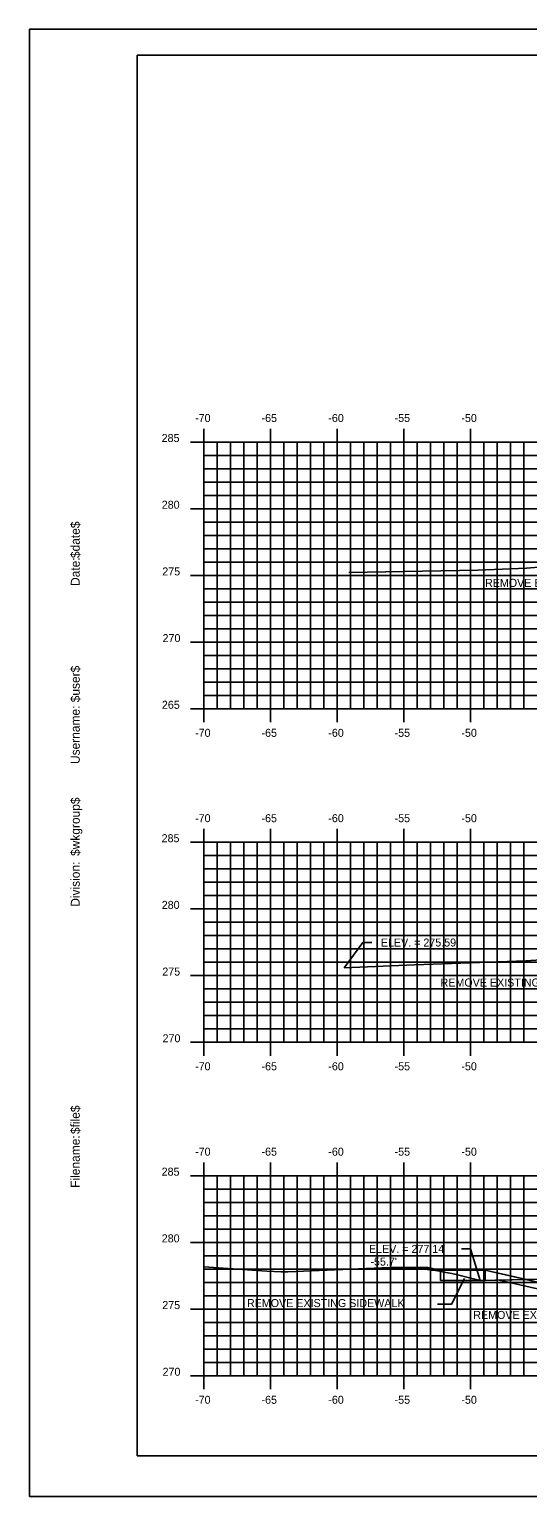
# Model space of a CAD drawing. Extents: x 854008 to 854178, y 366268 to 366378.
# Drawn here: x 854008 to 854045.4, y 366268.2 to 366378.2 of the extents above; entities that cross this region are included whole.
import ezdxf

# ---------------------------------------------------------------- set-up
doc = ezdxf.new("R2010")
doc.units = 0
for name, color, linetype in [('ANNOTATION', 7, 'Continuous'), ('BORDER', 7, 'Continuous'), ('D_Roadway_FinishedGrade', 7, 'Continuous'), ('D_Roadway_SubGrade', 7, 'Continuous'), ('D_Text_Standard', 7, 'Continuous'), ('H_V ANNOTATION', 7, 'Continuous'), ('JUNK COM EXC', 7, 'Continuous'), ('JUNK FILL', 7, 'Continuous'), ('MAJOR', 7, 'Continuous'), ('MINOR', 7, 'Continuous'), ('PLOT BOUNDARY', 7, 'Continuous'), ('S_Roadway_Centerline', 7, 'Continuous')]:
    doc.layers.add(name, color=color, linetype=linetype)

msp = doc.modelspace()

# ---------------------------------------------------------------- linework, layer by layer
at = {"layer": 'ANNOTATION'}
msp.add_lwpolyline([(854038.61, 366282.62), (854039.67, 366282.62), (854040.64, 366284.53)], dxfattribs=at)
at = {"layer": 'BORDER'}
for p, q in [((854176.1, 366376.24), (854016.1, 366376.24)), ((854016.1, 366376.24), (854016.1, 366271.24)), ((854016.1, 366271.24), (854176.1, 366271.24))]:
    msp.add_line(p, q, dxfattribs=at)
at = {"layer": 'D_Roadway_FinishedGrade'}
for p in [(854040.31, 366284.75), (854067.1, 366284.88)]:
    msp.add_line(p, (854041.81, 366284.38), dxfattribs=at)
msp.add_arc((854035.46, 366265.35), 20, 75.9638, 90.3035, dxfattribs=at)
at = {"layer": 'D_Roadway_SubGrade'}
msp.add_lwpolyline([(854043.23, 366284.41), (854046.34, 366283.7), (854046.88, 366283.57), (854050.76, 366283.59), (854057.27, 366283.69), (854058.44, 366283.75), (854067.1, 366283.91)], dxfattribs=at)
at = {"layer": 'D_Text_Standard'}
for points in [[(854031.62, 366307.83), (854033.01, 366309.72), (854033.69, 366309.72)], [(854041.81, 366284.38), (854041.1, 366286.75), (854040.42, 366286.75)]]:
    msp.add_lwpolyline(points, dxfattribs=at)
at = {"layer": 'JUNK COM EXC'}
for points in [[(854045.3, 366284.45), (854042.19, 366285.16), (854041.61, 366285.15), (854038.85, 366285.16), (854037.87, 366285.36), (854035.36, 366285.35)], [(854040.31, 366284.75), (854041.81, 366284.38), (854045.3, 366284.45)]]:
    msp.add_lwpolyline(points, dxfattribs=at)
msp.add_arc((854035.46, 366265.35), 20, 75.9638, 90.3035, dxfattribs=at)
at = {"layer": 'JUNK FILL'}
msp.add_lwpolyline([(854067.1, 366284.41), (854067.1, 366284.88), (854067.1, 366284.88), (854045.3, 366284.45), (854046.45, 366284.19), (854046.94, 366284.07), (854050.76, 366284.09), (854057.25, 366284.19), (854058.42, 366284.25), (854067.1, 366284.41)], dxfattribs=at)
at = {"layer": 'MAJOR'}
for p, q in [((854021.1, 366348.24), (854021.1, 366347.24)), ((854026.1, 366348.24), (854026.1, 366347.24)), ((854031.1, 366348.24), (854031.1, 366347.24)), ((854036.1, 366348.24), (854036.1, 366347.24)), ((854041.1, 366348.24), (854041.1, 366347.24)), ((854020.1, 366347.24), (854021.1, 366347.24)), ((854021.1, 366347.24), (854161.1, 366347.24)), ((854021.1, 366327.24), (854021.1, 366347.24)), ((854021.1, 366327.24), (854021.1, 366347.24)), ((854021.1, 366347.24), (854161.1, 366347.24)), ((854026.1, 366327.24), (854026.1, 366347.24)), ((854031.1, 366327.24), (854031.1, 366347.24)), ((854036.1, 366327.24), (854036.1, 366347.24)), ((854041.1, 366327.24), (854041.1, 366347.24)), ((854020.1, 366342.24), (854021.1, 366342.24)), ((854021.1, 366342.24), (854161.1, 366342.24)), ((854020.1, 366337.24), (854021.1, 366337.24)), ((854021.1, 366337.24), (854161.1, 366337.24)), ((854020.1, 366332.24), (854021.1, 366332.24)), ((854021.1, 366332.24), (854161.1, 366332.24)), ((854020.1, 366327.24), (854021.1, 366327.24)), ((854021.1, 366327.24), (854161.1, 366327.24)), ((854021.1, 366327.24), (854161.1, 366327.24)), ((854021.1, 366326.23), (854021.1, 366327.24)), ((854026.1, 366326.23), (854026.1, 366327.24)), ((854031.1, 366326.23), (854031.1, 366327.24)), ((854036.1, 366326.23), (854036.1, 366327.24)), ((854041.1, 366326.23), (854041.1, 366327.24)), ((854021.1, 366318.24), (854021.1, 366317.24)), ((854026.1, 366318.24), (854026.1, 366317.24)), ((854031.1, 366318.24), (854031.1, 366317.24)), ((854036.1, 366318.24), (854036.1, 366317.24)), ((854041.1, 366318.24), (854041.1, 366317.24)), ((854020.1, 366317.24), (854021.1, 366317.24)), ((854021.1, 366317.24), (854161.1, 366317.24)), ((854021.1, 366302.24), (854021.1, 366317.24)), ((854021.1, 366302.24), (854021.1, 366317.24)), ((854021.1, 366317.24), (854161.1, 366317.24)), ((854026.1, 366302.24), (854026.1, 366317.24)), ((854031.1, 366302.24), (854031.1, 366317.24)), ((854036.1, 366302.24), (854036.1, 366317.24)), ((854041.1, 366302.24), (854041.1, 366317.24)), ((854020.1, 366312.24), (854021.1, 366312.24)), ((854021.1, 366312.24), (854161.1, 366312.24)), ((854020.1, 366307.24), (854021.1, 366307.24)), ((854021.1, 366307.24), (854161.1, 366307.24)), ((854020.1, 366302.24), (854021.1, 366302.24)), ((854021.1, 366302.24), (854161.1, 366302.24)), ((854021.1, 366302.24), (854161.1, 366302.24)), ((854021.1, 366301.23), (854021.1, 366302.24)), ((854026.1, 366301.23), (854026.1, 366302.24)), ((854031.1, 366301.23), (854031.1, 366302.24)), ((854036.1, 366301.23), (854036.1, 366302.24)), ((854041.1, 366301.23), (854041.1, 366302.24)), ((854021.1, 366293.24), (854021.1, 366292.24)), ((854026.1, 366293.24), (854026.1, 366292.24)), ((854031.1, 366293.24), (854031.1, 366292.24)), ((854036.1, 366293.24), (854036.1, 366292.24)), ((854041.1, 366293.24), (854041.1, 366292.24)), ((854020.1, 366292.24), (854021.1, 366292.24)), ((854021.1, 366292.24), (854161.1, 366292.24)), ((854021.1, 366277.24), (854021.1, 366292.24)), ((854021.1, 366277.24), (854021.1, 366292.24)), ((854021.1, 366292.24), (854161.1, 366292.24)), ((854026.1, 366277.24), (854026.1, 366292.24)), ((854031.1, 366277.24), (854031.1, 366292.24)), ((854036.1, 366277.24), (854036.1, 366292.24)), ((854041.1, 366277.24), (854041.1, 366292.24)), ((854020.1, 366287.24), (854021.1, 366287.24)), ((854021.1, 366287.24), (854161.1, 366287.24)), ((854020.1, 366282.24), (854021.1, 366282.24)), ((854021.1, 366282.24), (854161.1, 366282.24)), ((854020.1, 366277.24), (854021.1, 366277.24)), ((854021.1, 366277.24), (854161.1, 366277.24)), ((854021.1, 366277.24), (854161.1, 366277.24)), ((854021.1, 366276.23), (854021.1, 366277.24)), ((854026.1, 366276.23), (854026.1, 366277.24)), ((854031.1, 366276.23), (854031.1, 366277.24)), ((854036.1, 366276.23), (854036.1, 366277.24)), ((854041.1, 366276.23), (854041.1, 366277.24))]:
    msp.add_line(p, q, dxfattribs=at)
at = {"layer": 'MINOR'}
for p, q in [((854021.1, 366327.24), (854021.1, 366347.24)), ((854021.1, 366346.24), (854161.1, 366346.24)), ((854021.1, 366346.24), (854022.11, 366346.24)), ((854022.1, 366327.24), (854022.1, 366347.24)), ((854023.1, 366327.24), (854023.1, 366347.24)), ((854024.1, 366327.24), (854024.1, 366347.24)), ((854025.1, 366327.24), (854025.1, 366347.24)), ((854027.1, 366327.24), (854027.1, 366347.24)), ((854028.1, 366327.24), (854028.1, 366347.24)), ((854029.1, 366327.24), (854029.1, 366347.24)), ((854030.1, 366327.24), (854030.1, 366347.24)), ((854032.1, 366327.24), (854032.1, 366347.24)), ((854033.1, 366327.24), (854033.1, 366347.24)), ((854034.1, 366327.24), (854034.1, 366347.24)), ((854035.1, 366327.24), (854035.1, 366347.24)), ((854037.1, 366327.24), (854037.1, 366347.24)), ((854038.1, 366327.24), (854038.1, 366347.24)), ((854039.1, 366327.24), (854039.1, 366347.24)), ((854040.1, 366327.24), (854040.1, 366347.24)), ((854042.1, 366327.24), (854042.1, 366347.24)), ((854043.1, 366327.24), (854043.1, 366347.24)), ((854044.1, 366327.24), (854044.1, 366347.24)), ((854045.1, 366327.24), (854045.1, 366347.24)), ((854021.1, 366345.24), (854161.1, 366345.24)), ((854021.1, 366345.24), (854022.11, 366345.24)), ((854021.1, 366344.24), (854161.1, 366344.24)), ((854021.1, 366344.24), (854022.11, 366344.24)), ((854021.1, 366343.24), (854161.1, 366343.24)), ((854021.1, 366343.24), (854022.11, 366343.24)), ((854021.1, 366341.24), (854161.1, 366341.24)), ((854021.1, 366341.24), (854022.11, 366341.24)), ((854021.1, 366340.24), (854161.1, 366340.24)), ((854021.1, 366340.24), (854022.11, 366340.24)), ((854021.1, 366339.24), (854161.1, 366339.24)), ((854021.1, 366339.24), (854022.11, 366339.24)), ((854021.1, 366338.24), (854161.1, 366338.24)), ((854021.1, 366338.24), (854022.11, 366338.24)), ((854021.1, 366336.24), (854161.1, 366336.24)), ((854021.1, 366336.24), (854022.11, 366336.24)), ((854021.1, 366335.24), (854161.1, 366335.24)), ((854021.1, 366335.24), (854022.11, 366335.24)), ((854021.1, 366334.24), (854161.1, 366334.24)), ((854021.1, 366334.24), (854022.11, 366334.24)), ((854021.1, 366333.24), (854161.1, 366333.24)), ((854021.1, 366333.24), (854022.11, 366333.24)), ((854021.1, 366331.24), (854161.1, 366331.24)), ((854021.1, 366331.24), (854022.11, 366331.24)), ((854021.1, 366330.24), (854161.1, 366330.24)), ((854021.1, 366330.24), (854022.11, 366330.24)), ((854021.1, 366329.24), (854161.1, 366329.24)), ((854021.1, 366329.24), (854022.11, 366329.24)), ((854021.1, 366328.24), (854161.1, 366328.24)), ((854021.1, 366328.24), (854022.11, 366328.24)), ((854022.1, 366302.24), (854022.1, 366317.24)), ((854023.1, 366302.24), (854023.1, 366317.24)), ((854024.1, 366302.24), (854024.1, 366317.24)), ((854025.1, 366302.24), (854025.1, 366317.24)), ((854027.1, 366302.24), (854027.1, 366317.24)), ((854028.1, 366302.24), (854028.1, 366317.24)), ((854029.1, 366302.24), (854029.1, 366317.24)), ((854030.1, 366302.24), (854030.1, 366317.24)), ((854032.1, 366302.24), (854032.1, 366317.24)), ((854033.1, 366302.24), (854033.1, 366317.24)), ((854034.1, 366302.24), (854034.1, 366317.24)), ((854035.1, 366302.24), (854035.1, 366317.24)), ((854037.1, 366302.24), (854037.1, 366317.24)), ((854038.1, 366302.24), (854038.1, 366317.24)), ((854039.1, 366302.24), (854039.1, 366317.24)), ((854040.1, 366302.24), (854040.1, 366317.24)), ((854042.1, 366302.24), (854042.1, 366317.24)), ((854043.1, 366302.24), (854043.1, 366317.24)), ((854044.1, 366302.24), (854044.1, 366317.24)), ((854045.1, 366302.24), (854045.1, 366317.24)), ((854021.1, 366316.24), (854161.1, 366316.24)), ((854021.1, 366316.24), (854022.11, 366316.24)), ((854021.1, 366315.24), (854161.1, 366315.24)), ((854021.1, 366315.24), (854022.11, 366315.24)), ((854021.1, 366314.24), (854161.1, 366314.24)), ((854021.1, 366314.24), (854022.11, 366314.24)), ((854021.1, 366313.24), (854161.1, 366313.24)), ((854021.1, 366313.24), (854022.11, 366313.24)), ((854021.1, 366311.24), (854161.1, 366311.24)), ((854021.1, 366311.24), (854022.11, 366311.24)), ((854021.1, 366310.24), (854161.1, 366310.24)), ((854021.1, 366310.24), (854022.11, 366310.24)), ((854021.1, 366309.24), (854161.1, 366309.24)), ((854021.1, 366309.24), (854022.11, 366309.24)), ((854021.1, 366308.24), (854161.1, 366308.24)), ((854021.1, 366308.24), (854022.11, 366308.24)), ((854021.1, 366306.24), (854161.1, 366306.24)), ((854021.1, 366306.24), (854022.11, 366306.24)), ((854021.1, 366305.24), (854161.1, 366305.24)), ((854021.1, 366305.24), (854022.11, 366305.24)), ((854021.1, 366304.24), (854161.1, 366304.24)), ((854021.1, 366304.24), (854022.11, 366304.24)), ((854021.1, 366303.24), (854161.1, 366303.24)), ((854021.1, 366303.24), (854022.11, 366303.24)), ((854021.1, 366291.24), (854161.1, 366291.24)), ((854021.1, 366291.24), (854022.11, 366291.24)), ((854022.1, 366277.24), (854022.1, 366292.24)), ((854023.1, 366277.24), (854023.1, 366292.24)), ((854024.1, 366277.24), (854024.1, 366292.24)), ((854025.1, 366277.24), (854025.1, 366292.24)), ((854027.1, 366277.24), (854027.1, 366292.24)), ((854028.1, 366277.24), (854028.1, 366292.24)), ((854029.1, 366277.24), (854029.1, 366292.24)), ((854030.1, 366277.24), (854030.1, 366292.24)), ((854032.1, 366277.24), (854032.1, 366292.24)), ((854033.1, 366277.24), (854033.1, 366292.24)), ((854034.1, 366277.24), (854034.1, 366292.24)), ((854035.1, 366277.24), (854035.1, 366292.24)), ((854037.1, 366277.24), (854037.1, 366292.24)), ((854038.1, 366277.24), (854038.1, 366292.24)), ((854039.1, 366277.24), (854039.1, 366292.24)), ((854040.1, 366277.24), (854040.1, 366292.24)), ((854042.1, 366277.24), (854042.1, 366292.24)), ((854043.1, 366277.24), (854043.1, 366292.24)), ((854044.1, 366277.24), (854044.1, 366292.24)), ((854045.1, 366277.24), (854045.1, 366292.24)), ((854021.1, 366290.24), (854161.1, 366290.24)), ((854021.1, 366290.24), (854022.11, 366290.24)), ((854021.1, 366289.24), (854161.1, 366289.24)), ((854021.1, 366289.24), (854022.11, 366289.24)), ((854021.1, 366288.24), (854161.1, 366288.24)), ((854021.1, 366288.24), (854022.11, 366288.24)), ((854021.1, 366286.24), (854161.1, 366286.24)), ((854021.1, 366286.24), (854022.11, 366286.24)), ((854021.1, 366285.24), (854161.1, 366285.24)), ((854021.1, 366285.24), (854022.11, 366285.24)), ((854021.1, 366284.24), (854161.1, 366284.24)), ((854021.1, 366284.24), (854022.11, 366284.24)), ((854021.1, 366283.24), (854161.1, 366283.24)), ((854021.1, 366283.24), (854022.11, 366283.24)), ((854021.1, 366281.24), (854161.1, 366281.24)), ((854021.1, 366281.24), (854022.11, 366281.24)), ((854021.1, 366280.24), (854161.1, 366280.24)), ((854021.1, 366280.24), (854022.11, 366280.24)), ((854021.1, 366279.24), (854161.1, 366279.24)), ((854021.1, 366279.24), (854022.11, 366279.24)), ((854021.1, 366278.24), (854161.1, 366278.24)), ((854021.1, 366278.24), (854022.11, 366278.24))]:
    msp.add_line(p, q, dxfattribs=at)
at = {"layer": 'PLOT BOUNDARY'}
msp.add_lwpolyline([(854008.01, 366268.18), (854178.01, 366268.18), (854178.01, 366378.18), (854008.01, 366378.18)], close=True, dxfattribs=at)
at = {"layer": 'S_Roadway_Centerline'}
for p, q in [((854038.85, 366284.39), (854038.85, 366285.16)), ((854042.19, 366284.39), (854042.19, 366285.16))]:
    msp.add_line(p, q, dxfattribs=at)
for points in [[(854031.97, 366337.45), (854041.64, 366337.63), (854045.29, 366337.78), (854051.42, 366338.29)], [(854031.62, 366307.83), (854036.89, 366308.04), (854045.23, 366308.34), (854048.3, 366308.55)], [(854021.1, 366285.4), (854025.83, 366285.09), (854026.89, 366285.04), (854027.4, 366285.03), (854035.05, 366285.35), (854037.87, 366285.36), (854038.85, 366285.16), (854041.61, 366285.15), (854042.19, 366285.16), (854046.45, 366284.19)], [(854038.85, 366284.39), (854041.61, 366284.38), (854042.19, 366284.39)]]:
    msp.add_lwpolyline(points, dxfattribs=at)

# ---------------------------------------------------------------- texts
at = {"layer": 'ANNOTATION'}
for s, p in [('REMOVE EXISTING SIDEWALK', (854042.18, 366336.38)), ('REMOVE EXISTING SIDEWALK', (854038.85, 366306.42)), ('REMOVE EXISTING SIDEWALK', (854024.33, 366282.39)), ('REMOVE EXISTING PAVEMENT', (854041.3, 366281.5))]:
    msp.add_text(s, height=0.6, dxfattribs=at).set_placement(p)
at = {"layer": 'BORDER'}
for s, p in [('$date$', (854011.79, 366338.54)), ('Date:', (854011.79, 366336.45)), ('$user$', (854011.79, 366327.73)), ('Username:', (854011.79, 366323.1)), ('$wkgroup$', (854011.79, 366316.21)), ('Division:', (854011.79, 366312.4)), ('$file$', (854011.79, 366295.36)), ('Filename:', (854011.79, 366291.33))]:
    msp.add_text(s, height=0.67, rotation=90, dxfattribs=at).set_placement(p)
at = {"layer": 'D_Text_Standard'}
for s, p in [('ELEV. = 275.59', (854034.37, 366309.42)), ('ELEV. = 277.14', (854033.48, 366286.45)), ("-55.7'", (854033.59, 366285.5))]:
    msp.add_text(s, height=0.6, dxfattribs=at).set_placement(p)
at = {"layer": 'H_V ANNOTATION'}
for s, p in [('-70', (854020.44, 366348.74)), ('-65', (854025.42, 366348.74)), ('-60', (854030.43, 366348.74)), ('-55', (854035.4, 366348.74)), ('-50', (854040.41, 366348.74)), ('285', (854017.93, 366347.24)), ('280', (854017.94, 366342.24)), ('275', (854017.98, 366337.24)), ('270', (854018, 366332.24)), ('265', (854017.95, 366327.24)), ('-70', (854020.44, 366325.14)), ('-65', (854025.42, 366325.14)), ('-60', (854030.43, 366325.14)), ('-55', (854035.4, 366325.14)), ('-50', (854040.41, 366325.14)), ('-70', (854020.44, 366318.74)), ('-65', (854025.42, 366318.74)), ('-60', (854030.43, 366318.74)), ('-55', (854035.4, 366318.74)), ('-50', (854040.41, 366318.74)), ('285', (854017.93, 366317.24)), ('280', (854017.94, 366312.24)), ('275', (854017.98, 366307.24)), ('270', (854018, 366302.24)), ('-70', (854020.44, 366300.14)), ('-65', (854025.42, 366300.14)), ('-60', (854030.43, 366300.14)), ('-55', (854035.4, 366300.14)), ('-50', (854040.41, 366300.14)), ('-70', (854020.44, 366293.74)), ('-65', (854025.42, 366293.74)), ('-60', (854030.43, 366293.74)), ('-55', (854035.4, 366293.74)), ('-50', (854040.41, 366293.74)), ('285', (854017.93, 366292.24)), ('280', (854017.94, 366287.24)), ('275', (854017.98, 366282.24)), ('270', (854018, 366277.24)), ('-70', (854020.44, 366275.14)), ('-65', (854025.42, 366275.14)), ('-60', (854030.43, 366275.14)), ('-55', (854035.4, 366275.14)), ('-50', (854040.41, 366275.14))]:
    msp.add_text(s, height=0.6, dxfattribs=at).set_placement(p)
at = {"layer": 'MAJOR'}
for p in [(854021.1, 366327.24), (854021.1, 366302.24), (854021.1, 366277.24)]:
    msp.add_text('-', height=0.00000006, rotation=53.1301, dxfattribs=at).set_placement(p)

doc.saveas('drawing.dxf')
